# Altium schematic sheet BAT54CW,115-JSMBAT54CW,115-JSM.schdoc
size 127 x 101 mm
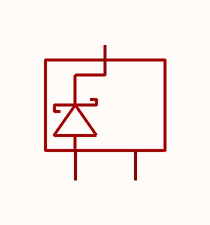
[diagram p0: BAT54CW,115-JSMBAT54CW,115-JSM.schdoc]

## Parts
D?  bat54cw,115-jsm  [SOT-323-3_L2.1-W1.3-P1.30-LS2.3-BR]  (value not drawn)

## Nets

Not connected (* = marked no-connect by the designer): D? 1(A) 2 3(K)

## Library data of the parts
D? = bat54cw,115-jsm: 二极管配置:1个独立式;正向压降(Vf):-;直流反向耐压(Vr):30V;整流电流:200mA;; Manufacturer: JSMSEMI(杰盛微); AddInBom: yes; ModelId: 81bbbbdf3145418d8c918b8f2fd0a837; ModelTransform: 90.551,78.74,0,0,0,0,0,0,0; Diode Configuration: 1个独立式; Voltage - DC Reverse(Vr): 30V; Current - Rectified: 200mA; Reverse Leakage Current (Ir): 2uA@25V; Non-Repetitive Peak Forward Surge Current: 600mA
